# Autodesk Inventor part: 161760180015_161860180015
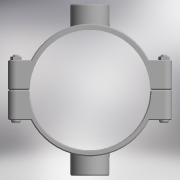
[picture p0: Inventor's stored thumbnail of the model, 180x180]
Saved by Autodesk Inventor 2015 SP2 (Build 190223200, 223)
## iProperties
Created: 2017-05
Part Number: 161760180015_161860180015
Material: Generic
Description: PLASSON DOUBLE SADDLE 180-1.1/2"
Document SubType Name: Modeling
Designer: KIM
Density: 1 g/cm^3
Appearance: Default
Author: KIM
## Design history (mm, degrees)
derived "16176.ipt"
feature "Solid1::16176.ipt"
feature "Solid2::16176.ipt"
tag "TaggingFeature1"
body "Solid1"
body "Solid2"
other parameters: "d0" = 198, "d1" = 245, "d4" = 154, "d5" = 0, "d6" = 12.25, "d7" = 245, "d8" = 0.1, "d10" = 0, "d11" = 1.8, "d20" = 1.8, "d23" = 1.8, "d36" = 15, "d37" = 12, "d38" = 98, "d39" = 0, "d40" = 3, "d41" = 5, "d42" = 0, "d44" = 3, "d45" = 0, "d46" = 1.8, "d52" = 44.845, "d53" = 25, "d54" = 0, "d57" = 0, "d58" = 194.4, "d60" = 0, "d62" = 15, "d63" = 12, "d67" = 256, "d68" = 58.2985, "d69" = 44.845, "d70" = 25, "d71" = 0, "d74" = 0, "d75" = 1.8, "G_" = 44.845, "A_" = 128, "L_" = 245, "L_1" = 154, "l_2" = 25
